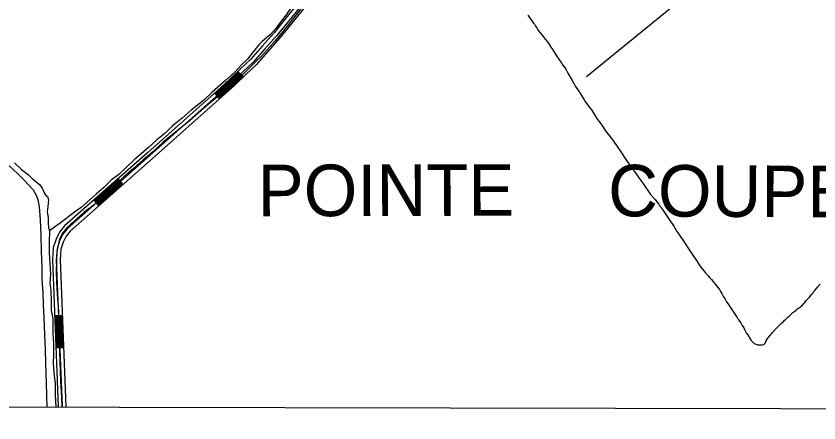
# Model space of a CAD drawing. Extents: x 3187622 to 3225504, y 800805 to 826213.
# Drawn here: x 3193318 to 3196432, y 806183 to 807762 of the extents above; entities that cross this region are included whole.
import ezdxf

# ---------------------------------------------------------------- set-up
doc = ezdxf.new("R2010")
doc.units = 0
for name, color, linetype in [('V-DTCH-CNTR', 7, 'Continuous'), ('V-GRID-FRAM', 7, 'Continuous'), ('V-ROAD-CNTR', 7, 'Continuous'), ('V-TOPO-GNAM-IDEN', 7, 'Continuous'), ('V-TOPO-SHOR', 7, 'Continuous')]:
    doc.layers.add(name, color=color, linetype=linetype)

msp = doc.modelspace()

# ---------------------------------------------------------------- linework, layer by layer
at = {"layer": 'V-DTCH-CNTR'}
for points in [[(3194532.2, 807920.2), (3194503.3, 807892.9), (3194479.8, 807869.2), (3194460.4, 807843.5), (3194437.3, 807807), (3194412.1, 807777.5), (3194393.9, 807753.9), (3194369.9, 807723.1), (3194349.5, 807696.9), (3194322.5, 807665.5), (3194301, 807641.5), (3194271.8, 807608.3), (3194247.4, 807584.3), (3194216.5, 807553.3), (3194185.6, 807523.6)], [(3192778.1, 807611), (3192825.2, 807569.5), (3192872.1, 807532.8), (3192915.2, 807497.5), (3192969.4, 807452.2), (3193015.1, 807415.6), (3193058.1, 807380.4), (3193093.8, 807347), (3193126.2, 807315.7), (3193163.1, 807286), (3193199.8, 807255.6), (3193249, 807215.8), (3193290.1, 807182.2), (3193323.5, 807152), (3193349, 807125), (3193367.8, 807105.6), (3193384.6, 807087.5), (3193396.8, 807067), (3193403.2, 807050.3), (3193407.6, 807022.5)], [(3194185.6, 807523.6), (3194149.5, 807491.8), (3194106.2, 807454.5), (3194065.2, 807420), (3194024.1, 807385.5), (3193981.3, 807348.6), (3193937.4, 807312.9), (3193889, 807272.6), (3193847.7, 807234.4)], [(3193847.7, 807234.4), (3193810.7, 807204.4), (3193773.8, 807171.1), (3193734.3, 807137.1), (3193705.8, 807106.8), (3193661.4, 807065.6), (3193622.5, 807031.4), (3193581.5, 807000.2), (3193546.4, 806969.7), (3193515.1, 806940.1)], [(3193407.6, 807022.5), (3193412, 806972.1), (3193414.6, 806912), (3193415.9, 806849.6), (3193418.5, 806786.5), (3193418.3, 806740.1), (3193421.4, 806689.3), (3193423.4, 806643.4), (3193426.2, 806593.5), (3193428.7, 806525.1), (3193431.2, 806469.5), (3193433, 806414.8), (3193434.8, 806339.3), (3193436, 806288.1), (3193437.9, 806244.1)], [(3193515.1, 806940.1), (3193499.4, 806921.8), (3193486.7, 806897.2), (3193480.9, 806872.8), (3193476.1, 806847), (3193474.6, 806811.2), (3193474.2, 806772.5), (3193475, 806729.2), (3193477.7, 806682.8), (3193482.2, 806617.7), (3193485.3, 806547.3)], [(3193485.3, 806547.3), (3193485.5, 806495.7), (3193488.4, 806421.9), (3193490.5, 806344.2), (3193493.9, 806283), (3193495.8, 806244)]]:
    msp.add_lwpolyline(points, dxfattribs=at)
at = {"layer": 'V-GRID-FRAM'}
msp.add_lwpolyline([(3191838.8, 824434.1), (3223248.6, 824370.1), (3223219.5, 806183.5), (3191793.9, 806247.5), (3191838.8, 824434.1)], dxfattribs=at)
at = {"layer": 'V-ROAD-CNTR'}
for p, q in [((3194199.8, 807526.4), (3194178.9, 807547.9)), ((3194107.5, 807441.2), (3194087.5, 807463.6)), ((3193733.6, 807109.1), (3193713.7, 807131.7)), ((3193639.7, 807026.5), (3193619.9, 807049)), ((3193497.7, 806600), (3193467.7, 806598.9)), ((3193502.6, 806475.1), (3193472.6, 806474))]:
    msp.add_line(p, q, dxfattribs=at)
for points in [[(3194420.8, 807822.7), (3194348.4, 807733.3), (3194318.8, 807697.4), (3194272.3, 807645), (3194227.3, 807594.4), (3194189.2, 807557.9), (3194146.5, 807516.6), (3194097.8, 807472.8), (3193827.8, 807232.1), (3193506.2, 806948.9), (3193487.1, 806924.4), (3193473.4, 806896.4), (3193462.4, 806863.2), (3193459.1, 806816.7), (3193481.6, 806246.7)], [(3194432.5, 807813.2), (3194360, 807723.8), (3194330.2, 807687.6), (3194283.6, 807635), (3194238.1, 807584), (3194199.6, 807547.1), (3194156.7, 807505.6), (3194107.8, 807461.6), (3193837.7, 807220.9), (3193517.2, 806938.6), (3193499.9, 806916.4), (3193487.3, 806890.7), (3193477.2, 806860.2), (3193474.1, 806816.4), (3193496.7, 806246.7)], [(3194444.1, 807803.7), (3194371.6, 807714.3), (3194341.6, 807677.9), (3194294.8, 807625.1), (3194248.9, 807573.6), (3194210, 807536.3), (3194167, 807494.6), (3194117.8, 807450.4), (3193847.7, 807209.7), (3193528.2, 806928.3), (3193512.7, 806908.4), (3193501.2, 806885), (3193492.1, 806857.3), (3193489.1, 806816.2), (3193511.7, 806246.7)], [(3194181, 807545.8), (3194148.5, 807514.4), (3194099.8, 807470.5), (3194089.5, 807461.3)], [(3194183.1, 807543.6), (3194150.6, 807512.2), (3194101.8, 807468.3), (3194091.5, 807459.1)], [(3194185.2, 807541.5), (3194152.6, 807510), (3194103.8, 807466), (3194093.5, 807456.9)], [(3194187.3, 807539.3), (3194154.7, 807507.8), (3194105.8, 807463.8), (3194095.5, 807454.6)], [(3194189.3, 807537.2), (3194156.7, 807505.6), (3194107.8, 807461.6), (3194097.5, 807452.4)], [(3194191.4, 807535), (3194158.8, 807503.4), (3194109.8, 807459.3), (3194099.5, 807450.1)], [(3194193.5, 807532.8), (3194160.8, 807501.2), (3194111.8, 807457.1), (3194101.5, 807447.9)], [(3194195.6, 807530.7), (3194162.9, 807499), (3194113.8, 807454.9), (3194103.5, 807445.7)], [(3194197.7, 807528.5), (3194164.9, 807496.8), (3194115.8, 807452.6), (3194105.5, 807443.4)], [(3193715.7, 807129.4), (3193621.9, 807046.8)], [(3193717.7, 807127.2), (3193623.9, 807044.5)], [(3193719.7, 807124.9), (3193625.9, 807042.3)], [(3193721.7, 807122.7), (3193627.8, 807040)], [(3193723.6, 807120.4), (3193629.8, 807037.8)], [(3193725.6, 807118.2), (3193631.8, 807035.5)], [(3193727.6, 807115.9), (3193633.8, 807033.3)], [(3193729.6, 807113.6), (3193635.8, 807031)], [(3193731.6, 807111.4), (3193637.8, 807028.8)], [(3193470.7, 806599), (3193475.6, 806474.1)], [(3193473.7, 806599.1), (3193478.6, 806474.2)], [(3193476.7, 806599.2), (3193481.6, 806474.3)], [(3193479.7, 806599.3), (3193484.6, 806474.4)], [(3193482.7, 806599.5), (3193487.6, 806474.6)], [(3193485.7, 806599.6), (3193490.6, 806474.7)], [(3193488.7, 806599.7), (3193493.6, 806474.8)], [(3193491.7, 806599.8), (3193496.6, 806474.9)], [(3193494.7, 806599.9), (3193499.6, 806475)]]:
    msp.add_lwpolyline(points, dxfattribs=at)
at = {"layer": 'V-TOPO-SHOR'}
msp.add_line((3195531.3, 807527.3), (3196030.9, 807937.1), dxfattribs=at)
for points in [[(3194487.6, 807916.6), (3194465.6, 807898.7), (3194445.5, 807876.4), (3194423.1, 807853.2), (3194405.2, 807824.6), (3194387.4, 807800.1), (3194365.5, 807767.1), (3194346, 807742.7), (3194327.1, 807715.8), (3194304.2, 807689.3), (3194289.7, 807677.4), (3194273.1, 807664), (3194261.4, 807652.6), (3194237.8, 807624.1)], [(3195303.3, 807765.7), (3195325.9, 807735.2), (3195328.5, 807731), (3195333.4, 807723.8), (3195338, 807716.6), (3195345.1, 807704.8), (3195357.2, 807689.5), (3195372.3, 807670.9), (3195375.7, 807666.7), (3195382.9, 807657.2), (3195392.7, 807642.3), (3195399.8, 807631.7), (3195414.5, 807608.1), (3195432.6, 807581.8), (3195435.6, 807577.6), (3195443.9, 807565.4), (3195450.7, 807556.7), (3195459, 807541.1), (3195474.8, 807512.5), (3195486.1, 807493.9), (3195488.4, 807489.7), (3195493.3, 807481.7), (3195502, 807469.1), (3195507.2, 807460.8), (3195521.2, 807437.9), (3195524.2, 807432.6), (3195527.2, 807428.8), (3195533.6, 807420.4), (3195536.6, 807416.2), (3195543.4, 807406.7), (3195550.2, 807398), (3195557, 807388.8), (3195564.9, 807375.1), (3195570.9, 807365.2)], [(3194237.8, 807624.1), (3194215.7, 807595.2), (3194192.4, 807572.7), (3194166.6, 807545.2), (3194130.8, 807512.8), (3194079, 807467.5), (3194045.8, 807435.4), (3193997.6, 807397.2)], [(3193997.6, 807397.2), (3193962.4, 807366.2), (3193923.8, 807335.3), (3193896.2, 807307.6), (3193863.9, 807281.6), (3193831.4, 807252.6), (3193802.8, 807227.5), (3193775.7, 807204.4), (3193746.2, 807175.7), (3193716.6, 807147.6), (3193687.5, 807125.2), (3193658.8, 807096.9), (3193629.2, 807071.1)], [(3195570.9, 807365.2), (3195574.7, 807359.9), (3195589.8, 807339), (3195607.1, 807313.4), (3195614.3, 807303.9), (3195627.5, 807287.5), (3195635.5, 807276.9), (3195647.1, 807259.8), (3195663.4, 807235.8), (3195683.7, 807205.7), (3195697.3, 807184.8), (3195707.1, 807171.8), (3195720.3, 807154.7), (3195738, 807129.2), (3195746, 807119.3), (3195753.5, 807109), (3195759.9, 807098.3), (3195769, 807085), (3195779.5, 807070.2), (3195796.9, 807050), (3195803.3, 807042), (3195810.8, 807032.1), (3195814.6, 807026.7), (3195818.8, 807022.2), (3195821, 807018.4), (3195828.6, 807007.7), (3195856.8, 806965.1), (3195861.7, 806958.2), (3195870.4, 806944.9), (3195881.7, 806927), (3195885.1, 806921.7), (3195894.2, 806908.7), (3195905.5, 806892), (3195933.4, 806850.5), (3195945.4, 806831.1), (3195954.5, 806817.8), (3195966.6, 806799.9), (3195974.5, 806788.1), (3195991.1, 806767.9), (3196003.5, 806753.4), (3196006.6, 806749.6), (3196015.2, 806740.4), (3196025.1, 806728.6), (3196031.5, 806721), (3196046.6, 806700.8), (3196051.1, 806693.6), (3196056.4, 806685.2), (3196062.8, 806673.4), (3196067.7, 806665.8), (3196074.1, 806654), (3196079, 806646.4), (3196095.9, 806621.7), (3196099.3, 806616), (3196104.6, 806607.6), (3196109.1, 806601.5), (3196114, 806593.9), (3196115.9, 806590.8), (3196117.8, 806588.2), (3196120.8, 806584), (3196129.1, 806571.4), (3196133.2, 806563.8), (3196135.1, 806561.2), (3196140.8, 806552.4), (3196144.9, 806544), (3196149.1, 806536.4), (3196150.6, 806533), (3196152.5, 806530.3), (3196157.4, 806522.3), (3196160, 806518.9), (3196161.9, 806515.9), (3196165.6, 806509.8), (3196167.9, 806506.4), (3196169.8, 806503.3), (3196174.7, 806498), (3196178.9, 806493.8), (3196181.1, 806491.5), (3196191.4, 806487.3), (3196194.4, 806486.5), (3196199.3, 806486.5), (3196207.7, 806487.2), (3196213, 806487.2), (3196217.5, 806487.9), (3196220.6, 806489.4), (3196223.3, 806493.2), (3196225.9, 806499.3), (3196227.9, 806503.4), (3196234.4, 806512.1), (3196240.8, 806520.1), (3196243.9, 806524.6), (3196249.6, 806531), (3196253.1, 806535.6), (3196263.7, 806547.3), (3196269.1, 806552.6), (3196274.4, 806557.5), (3196278.2, 806561.7), (3196283.6, 806566.9), (3196288.5, 806571.9), (3196295.8, 806579), (3196298.8, 806581.7), (3196302.2, 806584.3), (3196307.9, 806589.6)], [(3193311.8, 807192.9), (3193339.1, 807166.8), (3193366.4, 807146), (3193380.3, 807131.6), (3193394.1, 807121.8), (3193409.5, 807108.2), (3193419.1, 807094.5), (3193425.6, 807078.7), (3193432.5, 807068.7), (3193440.6, 807061.6), (3193444.1, 807049.3), (3193440.8, 807023.4), (3193438.6, 807002.2), (3193442.9, 806980.7), (3193442.9, 806958.2), (3193444.2, 806942.8), (3193447.9, 806929.1)], [(3193629.2, 807071.1), (3193593.4, 807040), (3193570.9, 807019.8), (3193545.1, 807000.8), (3193517, 806979.6), (3193488.9, 806959.3), (3193466.9, 806943.2), (3193447.9, 806929.1)], [(3193447.9, 806929.1), (3193446.4, 806884.8), (3193447, 806845.3), (3193449.3, 806802.5), (3193451.2, 806760.6), (3193449.7, 806724.7), (3193453.3, 806698.8), (3193454.4, 806655.4), (3193454.8, 806619.4), (3193461.2, 806590.3), (3193461, 806569), (3193460.9, 806532.6), (3193462.8, 806490.3), (3193463.1, 806449.6)], [(3196307.9, 806589.6), (3196311.8, 806593.4), (3196315.6, 806597.2), (3196327.4, 806608.1), (3196331.2, 806611.5), (3196335.8, 806615.3), (3196338.4, 806617.6), (3196343.8, 806621.7), (3196349.1, 806625.9), (3196352.9, 806629.3), (3196357.1, 806631.9), (3196360.5, 806634.2), (3196363.6, 806636.4), (3196367, 806639.8), (3196372.3, 806646.2), (3196377.3, 806651.5), (3196381.9, 806657.2), (3196385.3, 806660.6), (3196395.6, 806672), (3196404.8, 806682.9), (3196409.7, 806689), (3196412, 806692), (3196417, 806698), (3196423.1, 806705.6), (3196426.9, 806710.5), (3196437.6, 806722.2)], [(3193463.1, 806449.6), (3193462.3, 806416.5), (3193465.2, 806378), (3193470.4, 806336.4), (3193469.7, 806292.5), (3193472.5, 806244.1)]]:
    msp.add_lwpolyline(points, dxfattribs=at)

# ---------------------------------------------------------------- texts
at = {"layer": 'V-TOPO-GNAM-IDEN'}
for s, rotation, p in [('POINTE', 0.1282, (3194255.7, 806985.4)), ('COUPEE', 359.7282, (3195614.4, 806985.5))]:
    msp.add_text(s, height=200, rotation=rotation, dxfattribs=at).set_placement(p)

doc.saveas('drawing.dxf')
